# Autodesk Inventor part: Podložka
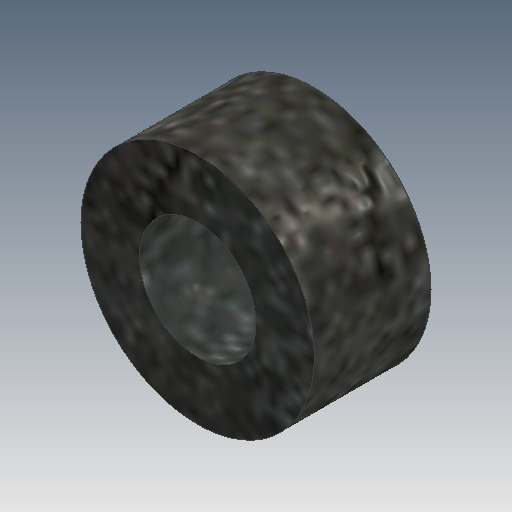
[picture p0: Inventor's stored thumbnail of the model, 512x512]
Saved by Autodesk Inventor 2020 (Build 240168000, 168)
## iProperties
Created: 2025-03
Part Number: Podložka
Material: Ocel
Document SubType Name: Modeling
Designer: doma
Density: 7.85 g/cm^3
Appearance: Plech
Mass: 18.4961 g
Surface Area: 14.1372 cm^2
Volume: 2.35619 cm^3
Author: doma
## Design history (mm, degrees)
sketch "Náčrt1"
  geometry: C1 r 10 at (0, 0); C2 r 5 at (0, 0); 1 further point
  constraints: 2 centre point, 2 coincident
  dimensions: "d0" = 20 diameter of C1; "d1" = 10 diameter of C2
extrude "Vysunutí1" new body sketch "Náčrt1" distance "d2" = 10; taper "d3" = 0 deg
node "Těleso1"
